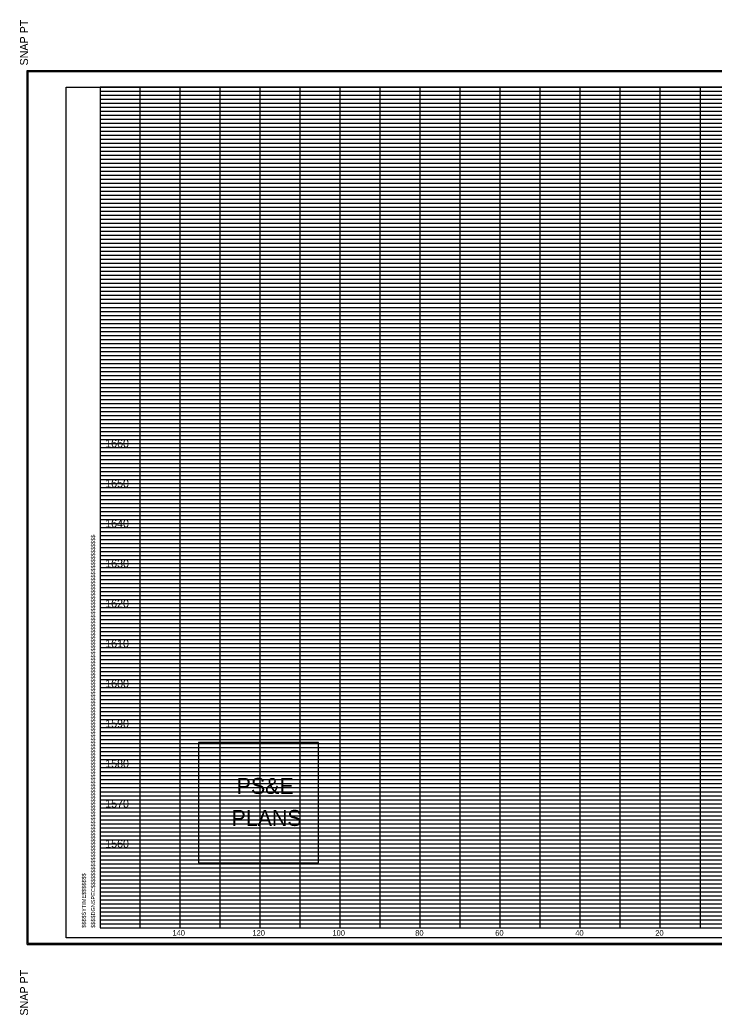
# Model space of a CAD drawing. Extents: x 980 to 1324, y 978 to 1767.
# Drawn here: x 979.9 to 1153.4, y 1518.2 to 1766.8 of the extents above; entities that cross this region are included whole.
import ezdxf

# ---------------------------------------------------------------- set-up
doc = ezdxf.new("R2010")
doc.units = 0
for name, color, linetype in [('DESIGN - SHEET - Corner Text', 7, 'Continuous'), ('DESIGN - SHEET - Light Grid', 7, 'Continuous'), ('DESIGN - SHEET - Linework', 7, 'Continuous'), ('DESIGN - SHEET - Plot Shape', 7, 'Continuous'), ('DESIGN - TYPICAL - Finished Grade and Subgrade', 7, 'Continuous')]:
    doc.layers.add(name, color=color, linetype=linetype)

# ---------------------------------------------------------------- blocks, each defined once
blk = doc.blocks.new('XSTSHT')
at = {"layer": 'DESIGN - SHEET - Light Grid'}
for p, q in [((0, 20.9), (8, 20.9)), ((8, 20.9), (16, 20.9)), ((0, 20.8), (8, 20.8)), ((0, 20.7), (8, 20.7)), ((8, 20.8), (16, 20.8)), ((8, 20.7), (16, 20.7)), ((0, 20.6), (8, 20.6)), ((0, 20.5), (8, 20.5)), ((0, 20.4), (8, 20.4)), ((8, 20.6), (16, 20.6)), ((8, 20.5), (16, 20.5)), ((8, 20.4), (16, 20.4)), ((0, 20.3), (8, 20.3)), ((0, 20.2), (8, 20.2)), ((8, 20.3), (16, 20.3)), ((8, 20.2), (16, 20.2)), ((0, 20.1), (8, 20.1)), ((0, 19.9), (8, 19.9)), ((8, 20.1), (16, 20.1)), ((8, 19.9), (16, 19.9)), ((0, 19.8), (8, 19.8)), ((0, 19.7), (8, 19.7)), ((8, 19.8), (16, 19.8)), ((8, 19.7), (16, 19.7)), ((0, 19.6), (8, 19.6)), ((0, 19.5), (8, 19.5)), ((0, 19.4), (8, 19.4)), ((8, 19.6), (16, 19.6)), ((8, 19.5), (16, 19.5)), ((8, 19.4), (16, 19.4)), ((0, 19.3), (8, 19.3)), ((0, 19.2), (8, 19.2)), ((8, 19.3), (16, 19.3)), ((8, 19.2), (16, 19.2)), ((0, 19.1), (8, 19.1)), ((0, 18.9), (8, 18.9)), ((8, 19.1), (16, 19.1)), ((8, 18.9), (16, 18.9)), ((0, 18.8), (8, 18.8)), ((0, 18.7), (8, 18.7)), ((8, 18.8), (16, 18.8)), ((8, 18.7), (16, 18.7)), ((0, 18.6), (8, 18.6)), ((0, 18.5), (8, 18.5)), ((0, 18.4), (8, 18.4)), ((8, 18.6), (16, 18.6)), ((8, 18.5), (16, 18.5)), ((8, 18.4), (16, 18.4)), ((0, 18.3), (8, 18.3)), ((0, 18.2), (8, 18.2)), ((8, 18.3), (16, 18.3)), ((8, 18.2), (16, 18.2)), ((0, 18.1), (8, 18.1)), ((8, 18.1), (16, 18.1)), ((0, 17.9), (8, 17.9)), ((0, 17.8), (8, 17.8)), ((0, 17.7), (8, 17.7)), ((8, 17.9), (16, 17.9)), ((8, 17.8), (16, 17.8)), ((8, 17.7), (16, 17.7)), ((0, 17.6), (8, 17.6)), ((0, 17.5), (8, 17.5)), ((8, 17.6), (16, 17.6)), ((8, 17.5), (16, 17.5)), ((0, 17.4), (8, 17.4)), ((0, 17.3), (8, 17.3)), ((0, 17.2), (8, 17.2)), ((8, 17.4), (16, 17.4)), ((8, 17.3), (16, 17.3)), ((8, 17.2), (16, 17.2)), ((0, 17.1), (8, 17.1)), ((8, 17.1), (16, 17.1)), ((0, 16.9), (8, 16.9)), ((0, 16.8), (8, 16.8)), ((0, 16.7), (8, 16.7)), ((8, 16.9), (16, 16.9)), ((8, 16.8), (16, 16.8)), ((8, 16.7), (16, 16.7)), ((0, 16.6), (8, 16.6)), ((0, 16.5), (8, 16.5)), ((8, 16.6), (16, 16.6)), ((8, 16.5), (16, 16.5)), ((0, 16.4), (8, 16.4)), ((0, 16.3), (8, 16.3)), ((0, 16.2), (8, 16.2)), ((8, 16.4), (16, 16.4)), ((8, 16.3), (16, 16.3)), ((8, 16.2), (16, 16.2)), ((0, 16.1), (8, 16.1)), ((8, 16.1), (16, 16.1)), ((0, 15.9), (8, 15.9)), ((0, 15.8), (8, 15.8)), ((0, 15.7), (8, 15.7)), ((8, 15.9), (16, 15.9)), ((8, 15.8), (16, 15.8)), ((8, 15.7), (16, 15.7)), ((0, 15.6), (8, 15.6)), ((0, 15.5), (8, 15.5)), ((8, 15.6), (16, 15.6)), ((8, 15.5), (16, 15.5)), ((0, 15.4), (8, 15.4)), ((0, 15.3), (8, 15.3)), ((0, 15.2), (8, 15.2)), ((8, 15.4), (16, 15.4)), ((8, 15.3), (16, 15.3)), ((8, 15.2), (16, 15.2)), ((0, 15.1), (8, 15.1)), ((8, 15.1), (16, 15.1)), ((0, 14.9), (8, 14.9)), ((0, 14.8), (8, 14.8)), ((0, 14.7), (8, 14.7)), ((8, 14.9), (16, 14.9)), ((8, 14.8), (16, 14.8)), ((8, 14.7), (16, 14.7)), ((0, 14.6), (8, 14.6)), ((0, 14.5), (8, 14.5)), ((8, 14.6), (16, 14.6)), ((8, 14.5), (16, 14.5)), ((0, 14.4), (8, 14.4)), ((0, 14.3), (8, 14.3)), ((0, 14.2), (8, 14.2)), ((8, 14.4), (16, 14.4)), ((8, 14.3), (16, 14.3)), ((8, 14.2), (16, 14.2)), ((0, 14.1), (8, 14.1)), ((8, 14.1), (16, 14.1)), ((0, 13.9), (8, 13.9)), ((0, 13.8), (8, 13.8)), ((0, 13.7), (8, 13.7)), ((8, 13.9), (16, 13.9)), ((8, 13.8), (16, 13.8)), ((8, 13.7), (16, 13.7)), ((0, 13.6), (8, 13.6)), ((0, 13.5), (8, 13.5)), ((8, 13.6), (16, 13.6)), ((8, 13.5), (16, 13.5)), ((0, 13.4), (8, 13.4)), ((0, 13.3), (8, 13.3)), ((0, 13.2), (8, 13.2)), ((8, 13.4), (16, 13.4)), ((8, 13.3), (16, 13.3)), ((8, 13.2), (16, 13.2)), ((0, 13.1), (8, 13.1)), ((8, 13.1), (16, 13.1)), ((0, 12.9), (8, 12.9)), ((0, 12.8), (8, 12.8)), ((0, 12.7), (8, 12.7)), ((8, 12.9), (16, 12.9)), ((8, 12.8), (16, 12.8)), ((8, 12.7), (16, 12.7)), ((0, 12.6), (8, 12.6)), ((0, 12.5), (8, 12.5)), ((8, 12.6), (16, 12.6)), ((8, 12.5), (16, 12.5)), ((0, 12.4), (8, 12.4)), ((0, 12.3), (8, 12.3)), ((0, 12.2), (8, 12.2)), ((8, 12.4), (16, 12.4)), ((8, 12.3), (16, 12.3)), ((8, 12.2), (16, 12.2)), ((0, 12.1), (8, 12.1)), ((8, 12.1), (16, 12.1)), ((0, 11.9), (8, 11.9)), ((0, 11.8), (8, 11.8)), ((0, 11.7), (8, 11.7)), ((8, 11.9), (16, 11.9)), ((8, 11.8), (16, 11.8)), ((8, 11.7), (16, 11.7)), ((0, 11.6), (8, 11.6)), ((0, 11.5), (8, 11.5)), ((8, 11.6), (16, 11.6)), ((8, 11.5), (16, 11.5)), ((0, 11.4), (8, 11.4)), ((0, 11.3), (8, 11.3)), ((0, 11.2), (8, 11.2)), ((8, 11.4), (16, 11.4)), ((8, 11.3), (16, 11.3)), ((8, 11.2), (16, 11.2)), ((0, 11.1), (8, 11.1)), ((8, 11.1), (16, 11.1)), ((0, 10.9), (8, 10.9)), ((0, 10.8), (8, 10.8)), ((0, 10.7), (8, 10.7)), ((8, 10.9), (16, 10.9)), ((8, 10.8), (16, 10.8)), ((8, 10.7), (16, 10.7)), ((0, 10.6), (8, 10.6)), ((0, 10.5), (8, 10.5)), ((8, 10.6), (16, 10.6)), ((8, 10.5), (16, 10.5)), ((0, 10.4), (8, 10.4)), ((0, 10.3), (8, 10.3)), ((0, 10.2), (8, 10.2)), ((8, 10.4), (16, 10.4)), ((8, 10.3), (16, 10.3)), ((8, 10.2), (16, 10.2)), ((0, 10.1), (8, 10.1)), ((8, 10.1), (16, 10.1)), ((0, 9.9), (8, 9.9)), ((0, 9.8), (8, 9.8)), ((0, 9.7), (8, 9.7)), ((8, 9.9), (16, 9.9)), ((8, 9.8), (16, 9.8)), ((8, 9.7), (16, 9.7)), ((0, 9.6), (8, 9.6)), ((0, 9.5), (8, 9.5)), ((8, 9.6), (16, 9.6)), ((8, 9.5), (16, 9.5)), ((0, 9.4), (8, 9.4)), ((0, 9.3), (8, 9.3)), ((0, 9.2), (8, 9.2)), ((8, 9.4), (16, 9.4)), ((8, 9.3), (16, 9.3)), ((8, 9.2), (16, 9.2)), ((0, 9.1), (8, 9.1)), ((8, 9.1), (16, 9.1)), ((0, 8.9), (8, 8.9)), ((0, 8.8), (8, 8.8)), ((8, 8.9), (16, 8.9)), ((8, 8.8), (16, 8.8)), ((0, 8.7), (8, 8.7)), ((0, 8.6), (8, 8.6)), ((0, 8.5), (8, 8.5)), ((8, 8.7), (16, 8.7)), ((8, 8.6), (16, 8.6)), ((8, 8.5), (16, 8.5)), ((0, 8.4), (8, 8.4)), ((0, 8.3), (8, 8.3)), ((8, 8.4), (16, 8.4)), ((8, 8.3), (16, 8.3)), ((0, 8.2), (8, 8.2)), ((0, 8.1), (8, 8.1)), ((8, 8.2), (16, 8.2)), ((8, 8.1), (16, 8.1)), ((0, 7.9), (8, 7.9)), ((0, 7.8), (8, 7.8)), ((8, 7.9), (16, 7.9)), ((8, 7.8), (16, 7.8)), ((0, 7.7), (8, 7.7)), ((0, 7.6), (8, 7.6)), ((0, 7.5), (8, 7.5)), ((8, 7.7), (16, 7.7)), ((8, 7.6), (16, 7.6)), ((8, 7.5), (16, 7.5)), ((0, 7.4), (8, 7.4)), ((0, 7.3), (8, 7.3)), ((8, 7.4), (16, 7.4)), ((8, 7.3), (16, 7.3)), ((0, 7.2), (8, 7.2)), ((0, 7.1), (8, 7.1)), ((8, 7.2), (16, 7.2)), ((8, 7.1), (16, 7.1)), ((0, 6.9), (8, 6.9)), ((0, 6.8), (8, 6.8)), ((8, 6.9), (16, 6.9)), ((8, 6.8), (16, 6.8)), ((0, 6.7), (8, 6.7)), ((0, 6.6), (8, 6.6)), ((0, 6.5), (8, 6.5)), ((8, 6.7), (16, 6.7)), ((8, 6.6), (16, 6.6)), ((8, 6.5), (16, 6.5)), ((0, 6.4), (8, 6.4)), ((0, 6.3), (8, 6.3)), ((8, 6.4), (16, 6.4)), ((8, 6.3), (16, 6.3)), ((0, 6.2), (8, 6.2)), ((0, 6.1), (8, 6.1)), ((8, 6.2), (16, 6.2)), ((8, 6.1), (16, 6.1)), ((0, 5.9), (8, 5.9)), ((0, 5.8), (8, 5.8)), ((8, 5.9), (16, 5.9)), ((8, 5.8), (16, 5.8)), ((0, 5.7), (8, 5.7)), ((0, 5.6), (8, 5.6)), ((0, 5.5), (8, 5.5)), ((8, 5.7), (16, 5.7)), ((8, 5.6), (16, 5.6)), ((8, 5.5), (16, 5.5)), ((0, 5.4), (8, 5.4)), ((0, 5.3), (8, 5.3)), ((8, 5.4), (16, 5.4)), ((8, 5.3), (16, 5.3)), ((0, 5.2), (8, 5.2)), ((0, 5.1), (8, 5.1)), ((8, 5.2), (16, 5.2)), ((8, 5.1), (16, 5.1)), ((0, 4.9), (8, 4.9)), ((0, 4.8), (8, 4.8)), ((8, 4.9), (16, 4.9)), ((8, 4.8), (16, 4.8)), ((0, 4.7), (8, 4.7)), ((0, 4.6), (8, 4.6)), ((0, 4.5), (8, 4.5)), ((8, 4.7), (16, 4.7)), ((8, 4.6), (16, 4.6)), ((8, 4.5), (16, 4.5)), ((0, 4.4), (8, 4.4)), ((0, 4.3), (8, 4.3)), ((8, 4.4), (16, 4.4)), ((8, 4.3), (16, 4.3)), ((0, 4.2), (8, 4.2)), ((0, 4.1), (8, 4.1)), ((8, 4.2), (16, 4.2)), ((8, 4.1), (16, 4.1)), ((0, 3.9), (8, 3.9)), ((0, 3.8), (8, 3.8)), ((8, 3.9), (16, 3.9)), ((8, 3.8), (16, 3.8)), ((0, 3.7), (8, 3.7)), ((0, 3.6), (8, 3.6)), ((0, 3.5), (8, 3.5)), ((8, 3.7), (16, 3.7)), ((8, 3.6), (16, 3.6)), ((8, 3.5), (16, 3.5)), ((0, 3.4), (8, 3.4)), ((0, 3.3), (8, 3.3)), ((8, 3.4), (16, 3.4)), ((8, 3.3), (16, 3.3)), ((0, 3.2), (8, 3.2)), ((0, 3.1), (8, 3.1)), ((8, 3.2), (16, 3.2)), ((8, 3.1), (16, 3.1)), ((0, 2.9), (8, 2.9)), ((0, 2.8), (8, 2.8)), ((8, 2.9), (16, 2.9)), ((8, 2.8), (16, 2.8)), ((0, 2.7), (8, 2.7)), ((0, 2.6), (8, 2.6)), ((0, 2.5), (8, 2.5)), ((8, 2.7), (16, 2.7)), ((8, 2.6), (16, 2.6)), ((8, 2.5), (16, 2.5)), ((0, 2.4), (8, 2.4)), ((0, 2.3), (8, 2.3)), ((8, 2.4), (16, 2.4)), ((8, 2.3), (16, 2.3)), ((0, 2.2), (8, 2.2)), ((0, 2.1), (8, 2.1)), ((8, 2.2), (16, 2.2)), ((8, 2.1), (16, 2.1)), ((0, 1.9), (8, 1.9)), ((0, 1.8), (8, 1.8)), ((8, 1.9), (16, 1.9)), ((8, 1.8), (16, 1.8)), ((0, 1.7), (8, 1.7)), ((0, 1.6), (8, 1.6)), ((0, 1.5), (8, 1.5)), ((8, 1.7), (16, 1.7)), ((8, 1.6), (16, 1.6)), ((8, 1.5), (16, 1.5)), ((0, 1.4), (8, 1.4)), ((0, 1.3), (8, 1.3)), ((8, 1.4), (16, 1.4)), ((8, 1.3), (16, 1.3)), ((0, 1.2), (8, 1.2)), ((0, 1.1), (8, 1.1)), ((8, 1.2), (16, 1.2)), ((8, 1.1), (16, 1.1)), ((0, 0.9), (8, 0.9)), ((0, 0.8), (8, 0.8)), ((8, 0.9), (16, 0.9)), ((8, 0.8), (16, 0.8)), ((0, 0.7), (8, 0.7)), ((0, 0.6), (8, 0.6)), ((0, 0.5), (8, 0.5)), ((8, 0.7), (16, 0.7)), ((8, 0.6), (16, 0.6)), ((8, 0.5), (16, 0.5)), ((0, 0.4), (8, 0.4)), ((0, 0.3), (8, 0.3)), ((8, 0.4), (16, 0.4)), ((8, 0.3), (16, 0.3)), ((0, 0.2), (8, 0.2)), ((0, 0.1), (8, 0.1)), ((8, 0.2), (16, 0.2)), ((8, 0.1), (16, 0.1))]:
    blk.add_line(p, q, dxfattribs=at)
at = {"layer": 'DESIGN - SHEET - Linework'}
for p, q in [((-1.823, -0.414), (-1.823, 21.414)), ((-1.823, 21.414), (32.217, 21.414)), ((1, 0), (1, 21)), ((2, 0), (2, 21)), ((3, 0), (3, 21)), ((4, 0), (4, 21)), ((5, 0), (5, 21)), ((6, 0), (6, 21)), ((7, 0), (7, 21)), ((8, 0), (8, 21)), ((9, 0), (9, 21)), ((10, 0), (10, 21)), ((11, 0), (11, 21)), ((12, 0), (12, 21)), ((13, 0), (13, 21)), ((14, 0), (14, 21)), ((15, 0), (15, 21)), ((0, 20), (28, 20)), ((0, 19), (32, 19)), ((0, 18), (32, 18)), ((0, 17), (32, 17)), ((0, 16), (32, 16)), ((0, 15), (32, 15)), ((0, 14), (32, 14)), ((0, 13), (32, 13)), ((0, 12), (32, 12)), ((0, 11), (32, 11)), ((0, 10), (32, 10)), ((0, 9), (32, 9)), ((0, 8), (32, 8)), ((0, 7), (32, 7)), ((0, 6), (32, 6)), ((0, 5), (32, 5)), ((0, 4), (32, 4)), ((0, 3), (32, 3)), ((0, 2), (32, 2)), ((0, 1), (32, 1)), ((-1.823, -0.414), (32.217, -0.414))]:
    blk.add_line(p, q, dxfattribs=at)
blk.add_lwpolyline([(0, 21), (0, 0), (32, 0), (32, 21), (0, 21)], dxfattribs=at)
at = {"layer": 'DESIGN - SHEET - Plot Shape'}
for points in [[(-1.803, 21.394), (32.197, 21.394), (32.197, -0.394), (-1.803, -0.394)], [(-0.85, 21), (32, 21), (32, -0.25), (-0.85, -0.25)]]:
    blk.add_lwpolyline(points, close=True, dxfattribs=at)
at = {"layer": 'DESIGN - SHEET - Corner Text'}
for s, height, p in [('  SNAP PT', 0.2, (-1.803, 21.394)), ('$$$$DGNSPEC$$$$$$$$$$$$$$$$$$$$$$$$$$$$$$$$$$$$$$$$$$$$$$$$$$$$$$$$$$$$$$$$$$$$$$$$$$$$$$$$$$$$$$$$$$$$$$$$$$$$$$$$$$$$$$$$$$$', 0.100002, (-0.126, 0)), ('$$$$SYTIME$$$$$$$', 0.1, (-0.358, 0)), ('SNAP PT  ', 0.2, (-1.803, -2.194))]:
    blk.add_text(s, height=height, rotation=90, dxfattribs=at).set_placement(p)

msp = doc.modelspace()

# ---------------------------------------------------------------- linework, layer by layer
at = {"layer": 'DESIGN - SHEET - Corner Text'}
msp.add_lwpolyline([(1024.59, 1586.25), (1024.59, 1556.25), (1054.59, 1556.25), (1054.59, 1586.25)], close=True, dxfattribs=at)
at = {"layer": 'DESIGN - SHEET - Plot Shape'}
msp.add_lwpolyline([(991.5, 1750), (1320, 1750), (1320, 1537.5), (991.5, 1537.5)], close=True, dxfattribs=at)

# ---------------------------------------------------------------- block references
at = {"layer": 'DESIGN - TYPICAL - Finished Grade and Subgrade', "xscale": 10, "yscale": 10}
msp.add_blockref('XSTSHT', (1000, 1540), dxfattribs=at)

# ---------------------------------------------------------------- texts
at = {"layer": 'DESIGN - SHEET - Corner Text'}
for s, height, p in [('1660', 2, (1001.25, 1660)), ('1650', 2, (1001.25, 1650)), ('1640', 2, (1001.25, 1640)), ('1630', 2, (1001.25, 1630)), ('1620', 2, (1001.25, 1620)), ('1610', 2, (1001.25, 1610)), ('1600', 2, (1001.25, 1600)), ('1590', 2, (1001.25, 1590)), ('1580', 2, (1001.25, 1580)), ('PS&E', 4, (1034.11, 1573.43)), ('1570', 2, (1001.25, 1570)), ('PLANS', 4, (1032.82, 1565.43)), ('1560', 2, (1001.25, 1560)), ('140', 1.4, (1018.06, 1538)), ('120', 1.4, (1038.06, 1538)), ('100', 1.4, (1058.06, 1538)), ('80', 1.4, (1078.74, 1538)), ('60', 1.4, (1098.74, 1538)), ('40', 1.4, (1118.74, 1538)), ('20', 1.4, (1138.74, 1538))]:
    msp.add_text(s, height=height, dxfattribs=at).set_placement(p)

doc.saveas('drawing.dxf')
